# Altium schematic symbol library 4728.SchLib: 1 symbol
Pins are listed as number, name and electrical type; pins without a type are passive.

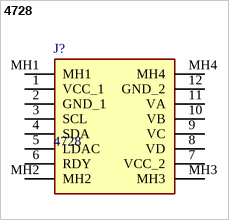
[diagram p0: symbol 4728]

## 4728
designator J?
Adafruit Accessories Replacement CSI/DSI Connector for Raspberry Pi - Repair Part; Geometry.Height: 4.6mm
footprint 4728
pins: 1 VCC_1, 2 GND_1, 3 SCL, 4 SDA, 5 LDAC, 6 RDY, 7 VCC_2, 8 VD, 9 VC, 10 VB, 11 VA, 12 GND_2, MH1, MH2, MH3, MH4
